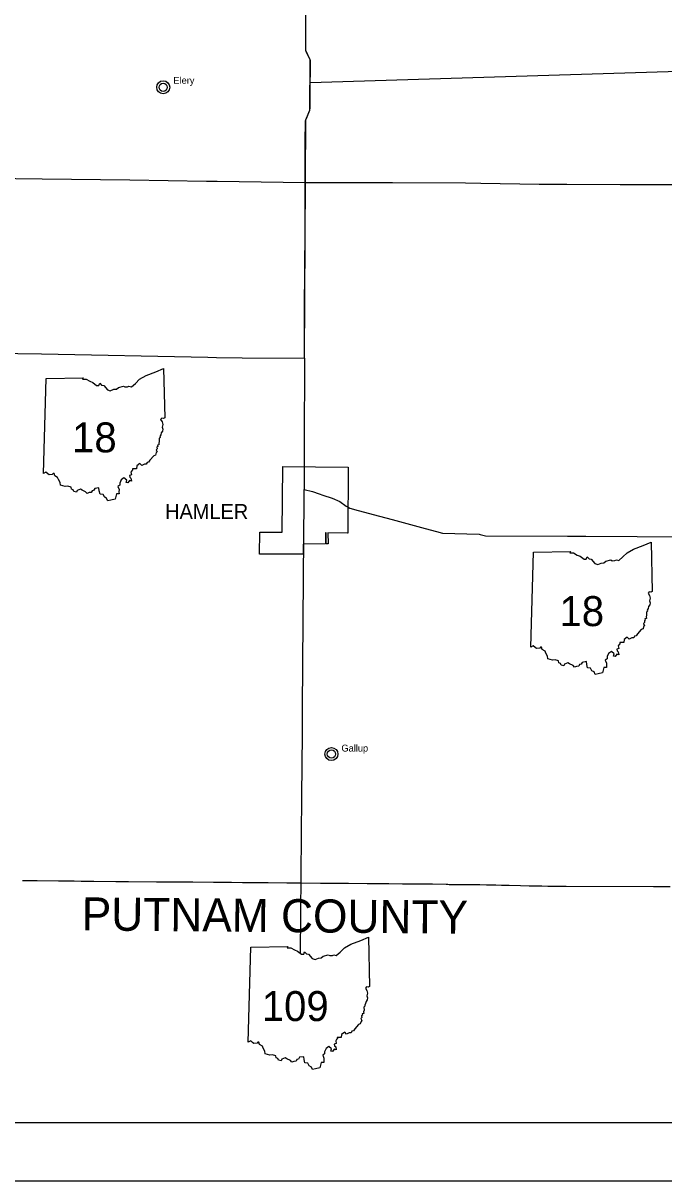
# Model space of a CAD drawing. Extents: x -62 to 810, y 0 to 440.
# Drawn here: x 310.9 to 421.2, y 0 to 199.3 of the extents above; entities that cross this region are included whole.
import ezdxf

# ---------------------------------------------------------------- set-up
doc = ezdxf.new("R2010")
doc.units = 0
for name, color, linetype in [('DV_X_Corp_Line', 7, 'Continuous'), ('GM_X_Adjacent_County_Text', 7, 'Continuous'), ('GM_X_Corporation_Text', 7, 'Continuous'), ('GM_X_County', 7, 'Continuous'), ('GM_X_State_Route', 7, 'Continuous'), ('PV_P_Text', 7, 'Continuous'), ('SH_Border', 7, 'Continuous'), ('SH_Cut_Line', 7, 'Continuous'), ('SH_Data', 7, 'Continuous'), ('SH_Text', 7, 'Continuous')]:
    doc.layers.add(name, color=color, linetype=linetype)

msp = doc.modelspace()

# ---------------------------------------------------------------- linework, layer by layer
at = {"layer": 'DV_X_Corp_Line'}
msp.add_lwpolyline([(351.66, 111.67), (355.46, 111.67), (355.59, 123), (366.85, 122.89), (366.8, 111.54), (366.73, 111.54), (363.35, 111.57), (363.38, 109.67), (363.07, 109.67), (363.07, 111.57), (362.92, 111.57), (362.92, 109.67), (359.12, 109.64), (359.09, 107.9), (355.36, 107.9), (351.6, 107.9)], close=True, dxfattribs=at)
for centre, radius in [((335, 188.28), 1.12), ((335, 188.28), 0.71), ((363.96, 73.49), 1.12), ((363.96, 73.49), 0.71)]:
    msp.add_circle(centre, radius, dxfattribs=at)
at = {"layer": 'GM_X_County'}
msp.add_lwpolyline([(310.77, 51.73), (313.34, 51.7), (317.01, 51.67), (319.67, 51.64), (320.86, 51.62), (323.04, 51.6), (326.88, 51.56), (329.03, 51.54), (333.87, 51.51), (334.27, 51.51), (337.68, 51.48), (340.12, 51.46), (343.65, 51.43), (346.75, 51.41), (348.67, 51.39), (350.87, 51.38), (353.07, 51.35), (356.3, 51.32), (358.75, 51.31), (358.78, 51.31), (362.05, 51.28), (363.97, 51.26), (366.23, 51.23), (366.9, 51.23), (370.08, 51.21), (373.83, 51.19), (376.16, 51.16), (381.35, 51.13), (383.69, 51.09), (383.93, 51.08), (384.01, 51.07), (384.23, 51.04), (384.37, 51.03), (388.07, 51.01), (388.79, 51), (388.87, 51), (389.28, 51.01), (389.49, 51.01), (390.64, 50.98), (392.27, 50.95), (393.21, 50.92), (393.91, 50.9), (394.57, 50.89), (396.49, 50.85), (397.99, 50.82), (399.11, 50.79), (400.14, 50.77), (401.22, 50.74), (402.67, 50.72), (403.42, 50.71), (404.09, 50.71), (404.33, 50.72), (419.38, 50.65), (419.65, 50.65), (420.14, 50.65), (422.24, 50.65)], dxfattribs=at)
at = {"layer": 'GM_X_State_Route'}
for points in [[(359.43, 171.91), (359.44, 180.11), (359.47, 181.2), (359.52, 182.5), (359.54, 182.65), (359.67, 182.93), (360.19, 184.2), (360.24, 184.32), (360.29, 184.75), (360.3, 187.08), (360.35, 192.84), (360.32, 193), (360.19, 193.26), (359.62, 194.44), (359.55, 194.64), (359.53, 195.17), (359.54, 202.27)], [(296.28, 172.8), (299.02, 172.75), (305.07, 172.65), (314.15, 172.51), (329.25, 172.33), (342.44, 172.14)], [(342.44, 172.14), (344.3, 172.11), (359.43, 171.91)], [(359.33, 144.8), (359.35, 150.27), (359.37, 156.78), (359.41, 163.71), (359.43, 169.07), (359.43, 171.91)], [(359.43, 171.91), (374.49, 171.9), (387.05, 171.82), (389.68, 171.77), (399.71, 171.62), (404.47, 171.59), (413.64, 171.54), (419.66, 171.53), (426.12, 171.52), (434.91, 171.57)], [(359.32, 141.66), (359.33, 144.8)], [(295.79, 142.57), (298.8, 142.55), (309.97, 142.42), (314.08, 142.4), (342.7, 141.81)], [(342.7, 141.81), (344.15, 141.77), (348.62, 141.7), (359.32, 141.66)], [(359.32, 141.66), (359.29, 126.7), (359.28, 122.43)], [(359.28, 122.43), (359.28, 122.15), (359.27, 119.01)], [(359.26, 117.79), (359.27, 117.98), (359.27, 119.01)], [(359.26, 116.99), (359.26, 117.79)], [(359.27, 119.01), (360.71, 118.66), (361.84, 118.29), (362.49, 118.08), (364.07, 117.56), (365.39, 116.98), (366.47, 116.16), (366.82, 115.97)], [(359.22, 111.6), (359.22, 111.6), (359.22, 112.56), (359.23, 113.43), (359.24, 114.37), (359.25, 115.41), (359.25, 116.04), (359.25, 116.22), (359.26, 116.77), (359.26, 116.99)], [(366.82, 115.97), (367.12, 115.81), (368.55, 115.42)], [(368.55, 115.42), (372.25, 114.43), (374.42, 113.84), (380.08, 112.32), (382.05, 111.78), (383.07, 111.51), (389.4, 111.32)], [(358.66, 39.16), (358.86, 66.24), (358.95, 76.89), (358.98, 81.38), (359.1, 96.45), (359.21, 110.82), (359.22, 111.6)], [(389.4, 111.32), (389.56, 111.31), (390.47, 111.04), (404.61, 111.01), (407.72, 110.99)], [(407.72, 110.99), (434.19, 110.83), (434.85, 110.83)]]:
    msp.add_lwpolyline(points, dxfattribs=at)
at = {"layer": 'PV_P_Text'}
for p, q in [((314.4, 121.77), (314.86, 138.14)), ((314.4, 121.77), (314.86, 138.14)), ((398.28, 91.86), (398.74, 108.24)), ((398.28, 91.86), (398.74, 108.24)), ((349.64, 23.86), (350.1, 40.23)), ((349.64, 23.86), (350.1, 40.23))]:
    msp.add_line(p, q, dxfattribs=at)
for points in [[(314.86, 138.14), (321.22, 138.25), (321.12, 138.05), (321.72, 138.01), (322.35, 137.66), (322.89, 137.44), (323.55, 136.92), (323.94, 136.92), (324.11, 137.35), (324.41, 137.02), (324.77, 136.96), (325.39, 136.18), (325.9, 136.01), (326.51, 136.28), (326.97, 136.32), (327.31, 136.59), (328.18, 136.81), (328.42, 136.68), (328.88, 136.7), (329.11, 136.8), (329.52, 136.71), (330.23, 137.31), (330.95, 138.01), (332.08, 138.67), (333.75, 139.3), (335.08, 139.86), (335.27, 131.37)], [(314.86, 138.14), (321.22, 138.25), (321.12, 138.05), (321.72, 138.01), (322.35, 137.66), (322.89, 137.44), (323.55, 136.92), (323.94, 136.92), (324.11, 137.35), (324.41, 137.02), (324.77, 136.96), (325.39, 136.18), (325.9, 136.01), (326.51, 136.28), (326.97, 136.32), (327.31, 136.59), (328.18, 136.81), (328.42, 136.68), (328.88, 136.7), (329.11, 136.8), (329.52, 136.71), (330.23, 137.31), (330.95, 138.01), (332.08, 138.67), (333.75, 139.3), (335.08, 139.86), (335.27, 131.37)], [(335.27, 131.37), (335.07, 131.25), (334.77, 131.3), (334.56, 131.06), (334.82, 130.67), (334.94, 130.25), (334.83, 129.78), (334.94, 129.4), (334.86, 129.08), (334.67, 128.76), (334.61, 128.46), (334.44, 128.14), (334.46, 127.96), (334.3, 127.82), (334.33, 127.29), (334.25, 126.99), (334.28, 126.74), (334.03, 126.67), (334.09, 126.46), (333.93, 126.3), (333.96, 126.02), (333.78, 125.85), (333.95, 125.49), (333.81, 125.38), (333.7, 124.94), (333.37, 124.85), (332.73, 124.06), (332.5, 123.76), (332.24, 123.69), (332.1, 123.38), (331.79, 123.38), (331.31, 123.16), (331, 123.53), (330.46, 123.09), (330.4, 122.58), (329.71, 122.6), (329.74, 122.34), (329.59, 122.26), (329.45, 122), (329.53, 121.54), (329.21, 121.43), (329.25, 121.16), (329.45, 121), (329.55, 120.49), (329.21, 120.59), (328.93, 120.16), (328.64, 120.26), (328.73, 120.63), (328.25, 121.06), (327.79, 120.71), (327.55, 120.15), (327.55, 119.78), (327.21, 119.55), (327.43, 119.02), (327.39, 118.65), (327.4, 118.3), (326.97, 118.31), (326.71, 117.37)], [(335.27, 131.37), (335.07, 131.25), (334.77, 131.3), (334.56, 131.06), (334.82, 130.67), (334.94, 130.25), (334.83, 129.78), (334.94, 129.4), (334.86, 129.08), (334.67, 128.76), (334.61, 128.46), (334.44, 128.14), (334.46, 127.96), (334.3, 127.82), (334.33, 127.29), (334.25, 126.99), (334.28, 126.74), (334.03, 126.67), (334.09, 126.46), (333.93, 126.3), (333.96, 126.02), (333.78, 125.85), (333.95, 125.49), (333.81, 125.38), (333.7, 124.94), (333.37, 124.85), (332.73, 124.06), (332.5, 123.76), (332.24, 123.69), (332.1, 123.38), (331.79, 123.38), (331.31, 123.16), (331, 123.53), (330.46, 123.09), (330.4, 122.58), (329.71, 122.6), (329.74, 122.34), (329.59, 122.26), (329.45, 122), (329.53, 121.54), (329.21, 121.43), (329.25, 121.16), (329.45, 121), (329.55, 120.49), (329.21, 120.59), (328.93, 120.16), (328.64, 120.26), (328.73, 120.63), (328.25, 121.06), (327.79, 120.71), (327.55, 120.15), (327.55, 119.78), (327.21, 119.55), (327.43, 119.02), (327.39, 118.65), (327.4, 118.3), (326.97, 118.31), (326.71, 117.37)], [(326.71, 117.37), (325.97, 117.19), (325.45, 117.09), (325.27, 117.51), (324.9, 117.74), (324.67, 118.17), (324.14, 118.23), (324.01, 118.82), (323.95, 119.3), (323.23, 119.18), (323.03, 118.88), (322.78, 118.81), (322.63, 118.51), (322.28, 118.49), (321.9, 118.35), (321.66, 118.64), (321.04, 118.93), (320.77, 119.08), (320.19, 118.84), (320.07, 118.57), (319.61, 118.69), (319.5, 119), (319.22, 119.09), (319.16, 119.42), (318.57, 119.59), (318.11, 119.52), (317.31, 119.78), (317.26, 120.21), (316.99, 120.73), (316.84, 121.1), (316.34, 121.37), (316.23, 121.81), (316.07, 121.79), (315.92, 121.62), (315.36, 121.54), (315.14, 121.71), (314.82, 122.02), (314.4, 121.77)], [(326.71, 117.37), (325.97, 117.19), (325.45, 117.09), (325.27, 117.51), (324.9, 117.74), (324.67, 118.17), (324.14, 118.23), (324.01, 118.82), (323.95, 119.3), (323.23, 119.18), (323.03, 118.88), (322.78, 118.81), (322.63, 118.51), (322.28, 118.49), (321.9, 118.35), (321.66, 118.64), (321.04, 118.93), (320.77, 119.08), (320.19, 118.84), (320.07, 118.57), (319.61, 118.69), (319.5, 119), (319.22, 119.09), (319.16, 119.42), (318.57, 119.59), (318.11, 119.52), (317.31, 119.78), (317.26, 120.21), (316.99, 120.73), (316.84, 121.1), (316.34, 121.37), (316.23, 121.81), (316.07, 121.79), (315.92, 121.62), (315.36, 121.54), (315.14, 121.71), (314.82, 122.02), (314.4, 121.77)], [(398.74, 108.24), (405.09, 108.34), (405, 108.14), (405.6, 108.1), (406.23, 107.75), (406.77, 107.53), (407.43, 107.01), (407.82, 107.02), (407.99, 107.44), (408.29, 107.12), (408.65, 107.06), (409.27, 106.27), (409.78, 106.1), (410.39, 106.37), (410.85, 106.42), (411.18, 106.68), (412.06, 106.91), (412.3, 106.77), (412.76, 106.8), (412.99, 106.9), (413.4, 106.81), (414.1, 107.41), (414.83, 108.11), (415.96, 108.77), (417.63, 109.4), (418.96, 109.96), (419.15, 101.46)], [(398.74, 108.24), (405.09, 108.34), (405, 108.14), (405.6, 108.1), (406.23, 107.75), (406.77, 107.53), (407.43, 107.01), (407.82, 107.02), (407.99, 107.44), (408.29, 107.12), (408.65, 107.06), (409.27, 106.27), (409.78, 106.1), (410.39, 106.37), (410.85, 106.42), (411.18, 106.68), (412.06, 106.91), (412.3, 106.77), (412.76, 106.8), (412.99, 106.9), (413.4, 106.81), (414.1, 107.41), (414.83, 108.11), (415.96, 108.77), (417.63, 109.4), (418.96, 109.96), (419.15, 101.46)], [(419.15, 101.46), (418.95, 101.34), (418.65, 101.4), (418.44, 101.16), (418.7, 100.76), (418.82, 100.34), (418.71, 99.88), (418.82, 99.5), (418.74, 99.18), (418.55, 98.86), (418.49, 98.56), (418.32, 98.24), (418.34, 98.06), (418.18, 97.92), (418.21, 97.39), (418.13, 97.09), (418.16, 96.84), (417.91, 96.77), (417.97, 96.56), (417.81, 96.4), (417.84, 96.12), (417.66, 95.94), (417.83, 95.58), (417.69, 95.47), (417.58, 95.04), (417.25, 94.95), (416.61, 94.16), (416.38, 93.86), (416.12, 93.78), (415.98, 93.47), (415.67, 93.47), (415.19, 93.26), (414.88, 93.63), (414.34, 93.19), (414.28, 92.68), (413.59, 92.69), (413.62, 92.43), (413.47, 92.36), (413.33, 92.1), (413.41, 91.64), (413.09, 91.52), (413.13, 91.26), (413.33, 91.09), (413.42, 90.58), (413.08, 90.69), (412.81, 90.26), (412.52, 90.36), (412.61, 90.72), (412.13, 91.16), (411.67, 90.81), (411.43, 90.25), (411.43, 89.87), (411.09, 89.64), (411.31, 89.11), (411.27, 88.74), (411.27, 88.4), (410.85, 88.41), (410.59, 87.47)], [(419.15, 101.46), (418.95, 101.34), (418.65, 101.4), (418.44, 101.16), (418.7, 100.76), (418.82, 100.34), (418.71, 99.88), (418.82, 99.5), (418.74, 99.18), (418.55, 98.86), (418.49, 98.56), (418.32, 98.24), (418.34, 98.06), (418.18, 97.92), (418.21, 97.39), (418.13, 97.09), (418.16, 96.84), (417.91, 96.77), (417.97, 96.56), (417.81, 96.4), (417.84, 96.12), (417.66, 95.94), (417.83, 95.58), (417.69, 95.47), (417.58, 95.04), (417.25, 94.95), (416.61, 94.16), (416.38, 93.86), (416.12, 93.78), (415.98, 93.47), (415.67, 93.47), (415.19, 93.26), (414.88, 93.63), (414.34, 93.19), (414.28, 92.68), (413.59, 92.69), (413.62, 92.43), (413.47, 92.36), (413.33, 92.1), (413.41, 91.64), (413.09, 91.52), (413.13, 91.26), (413.33, 91.09), (413.42, 90.58), (413.08, 90.69), (412.81, 90.26), (412.52, 90.36), (412.61, 90.72), (412.13, 91.16), (411.67, 90.81), (411.43, 90.25), (411.43, 89.87), (411.09, 89.64), (411.31, 89.11), (411.27, 88.74), (411.27, 88.4), (410.85, 88.41), (410.59, 87.47)], [(410.59, 87.47), (409.85, 87.29), (409.33, 87.18), (409.15, 87.61), (408.78, 87.83), (408.54, 88.26), (408.02, 88.32), (407.89, 88.91), (407.83, 89.39), (407.11, 89.27), (406.91, 88.98), (406.66, 88.9), (406.51, 88.61), (406.16, 88.58), (405.78, 88.44), (405.54, 88.73), (404.92, 89.02), (404.65, 89.17), (404.07, 88.94), (403.95, 88.66), (403.49, 88.79), (403.38, 89.09), (403.1, 89.19), (403.04, 89.51), (402.44, 89.68), (401.99, 89.62), (401.19, 89.88), (401.14, 90.31), (400.87, 90.83), (400.72, 91.19), (400.22, 91.47), (400.11, 91.9), (399.95, 91.89), (399.8, 91.71), (399.24, 91.63), (399.02, 91.81), (398.7, 92.11), (398.28, 91.86)], [(410.59, 87.47), (409.85, 87.29), (409.33, 87.18), (409.15, 87.61), (408.78, 87.83), (408.54, 88.26), (408.02, 88.32), (407.89, 88.91), (407.83, 89.39), (407.11, 89.27), (406.91, 88.98), (406.66, 88.9), (406.51, 88.61), (406.16, 88.58), (405.78, 88.44), (405.54, 88.73), (404.92, 89.02), (404.65, 89.17), (404.07, 88.94), (403.95, 88.66), (403.49, 88.79), (403.38, 89.09), (403.1, 89.19), (403.04, 89.51), (402.44, 89.68), (401.99, 89.62), (401.19, 89.88), (401.14, 90.31), (400.87, 90.83), (400.72, 91.19), (400.22, 91.47), (400.11, 91.9), (399.95, 91.89), (399.8, 91.71), (399.24, 91.63), (399.02, 91.81), (398.7, 92.11), (398.28, 91.86)], [(350.1, 40.23), (356.45, 40.34), (356.35, 40.14), (356.95, 40.1), (357.59, 39.75), (358.13, 39.53), (358.79, 39.01), (359.18, 39.01), (359.35, 39.44), (359.65, 39.11), (360.01, 39.05), (360.63, 38.27), (361.14, 38.1), (361.75, 38.36), (362.21, 38.41), (362.54, 38.67), (363.41, 38.9), (363.66, 38.77), (364.12, 38.79), (364.35, 38.89), (364.75, 38.8), (365.46, 39.4), (366.19, 40.1), (367.31, 40.76), (368.99, 41.39), (370.32, 41.95), (370.51, 33.45)], [(350.1, 40.23), (356.45, 40.34), (356.35, 40.14), (356.95, 40.1), (357.59, 39.75), (358.13, 39.53), (358.79, 39.01), (359.18, 39.01), (359.35, 39.44), (359.65, 39.11), (360.01, 39.05), (360.63, 38.27), (361.14, 38.1), (361.75, 38.36), (362.21, 38.41), (362.54, 38.67), (363.41, 38.9), (363.66, 38.77), (364.12, 38.79), (364.35, 38.89), (364.75, 38.8), (365.46, 39.4), (366.19, 40.1), (367.31, 40.76), (368.99, 41.39), (370.32, 41.95), (370.51, 33.45)], [(370.51, 33.45), (370.31, 33.34), (370.01, 33.39), (369.8, 33.15), (370.06, 32.76), (370.18, 32.34), (370.07, 31.87), (370.17, 31.49), (370.1, 31.17), (369.91, 30.85), (369.84, 30.55), (369.68, 30.23), (369.7, 30.05), (369.54, 29.91), (369.57, 29.38), (369.49, 29.08), (369.52, 28.83), (369.27, 28.76), (369.32, 28.55), (369.16, 28.39), (369.2, 28.11), (369.02, 27.93), (369.19, 27.58), (369.05, 27.46), (368.93, 27.03), (368.61, 26.94), (367.96, 26.15), (367.74, 25.85), (367.48, 25.78), (367.34, 25.47), (367.02, 25.47), (366.55, 25.25), (366.24, 25.62), (365.7, 25.18), (365.64, 24.67), (364.95, 24.68), (364.98, 24.43), (364.83, 24.35), (364.69, 24.09), (364.77, 23.63), (364.45, 23.52), (364.49, 23.25), (364.69, 23.09), (364.78, 22.58), (364.44, 22.68), (364.16, 22.25), (363.88, 22.35), (363.97, 22.71), (363.49, 23.15), (363.03, 22.8), (362.79, 22.24), (362.79, 21.86), (362.45, 21.64), (362.67, 21.1), (362.63, 20.74), (362.63, 20.39), (362.21, 20.4), (361.95, 19.46)], [(370.51, 33.45), (370.31, 33.34), (370.01, 33.39), (369.8, 33.15), (370.06, 32.76), (370.18, 32.34), (370.07, 31.87), (370.17, 31.49), (370.1, 31.17), (369.91, 30.85), (369.84, 30.55), (369.68, 30.23), (369.7, 30.05), (369.54, 29.91), (369.57, 29.38), (369.49, 29.08), (369.52, 28.83), (369.27, 28.76), (369.32, 28.55), (369.16, 28.39), (369.2, 28.11), (369.02, 27.93), (369.19, 27.58), (369.05, 27.46), (368.93, 27.03), (368.61, 26.94), (367.96, 26.15), (367.74, 25.85), (367.48, 25.78), (367.34, 25.47), (367.02, 25.47), (366.55, 25.25), (366.24, 25.62), (365.7, 25.18), (365.64, 24.67), (364.95, 24.68), (364.98, 24.43), (364.83, 24.35), (364.69, 24.09), (364.77, 23.63), (364.45, 23.52), (364.49, 23.25), (364.69, 23.09), (364.78, 22.58), (364.44, 22.68), (364.16, 22.25), (363.88, 22.35), (363.97, 22.71), (363.49, 23.15), (363.03, 22.8), (362.79, 22.24), (362.79, 21.86), (362.45, 21.64), (362.67, 21.1), (362.63, 20.74), (362.63, 20.39), (362.21, 20.4), (361.95, 19.46)], [(361.95, 19.46), (361.21, 19.28), (360.69, 19.17), (360.51, 19.6), (360.14, 19.83), (359.9, 20.26), (359.37, 20.32), (359.25, 20.91), (359.19, 21.38), (358.47, 21.27), (358.27, 20.97), (358.01, 20.89), (357.86, 20.6), (357.51, 20.57), (357.14, 20.44), (356.9, 20.72), (356.28, 21.02), (356, 21.17), (355.43, 20.93), (355.3, 20.66), (354.84, 20.78), (354.74, 21.09), (354.46, 21.18), (354.4, 21.5), (353.8, 21.68), (353.35, 21.61), (352.55, 21.87), (352.5, 22.3), (352.22, 22.82), (352.08, 23.19), (351.57, 23.46), (351.47, 23.9), (351.31, 23.88), (351.16, 23.71), (350.6, 23.63), (350.37, 23.8), (350.06, 24.1), (349.64, 23.86)], [(361.95, 19.46), (361.21, 19.28), (360.69, 19.17), (360.51, 19.6), (360.14, 19.83), (359.9, 20.26), (359.37, 20.32), (359.25, 20.91), (359.19, 21.38), (358.47, 21.27), (358.27, 20.97), (358.01, 20.89), (357.86, 20.6), (357.51, 20.57), (357.14, 20.44), (356.9, 20.72), (356.28, 21.02), (356, 21.17), (355.43, 20.93), (355.3, 20.66), (354.84, 20.78), (354.74, 21.09), (354.46, 21.18), (354.4, 21.5), (353.8, 21.68), (353.35, 21.61), (352.55, 21.87), (352.5, 22.3), (352.22, 22.82), (352.08, 23.19), (351.57, 23.46), (351.47, 23.9), (351.31, 23.88), (351.16, 23.71), (350.6, 23.63), (350.37, 23.8), (350.06, 24.1), (349.64, 23.86)]]:
    msp.add_lwpolyline(points, dxfattribs=at)
at = {"layer": 'SH_Border'}
msp.add_lwpolyline([(30, 430), (670, 430), (670, 10), (30, 10)], close=True, dxfattribs=at)
at = {"layer": 'SH_Cut_Line'}
msp.add_lwpolyline([(0, 0), (680, 0), (680, 440), (0, 440)], close=True, dxfattribs=at)
at = {"layer": 'SH_Data'}
msp.add_line((487.96, 193), (360.28, 189.02), dxfattribs=at)
at = {"layer": 'SH_Text'}
for p, q in [((359.55, 194.64), (359.54, 202.27)), ((360.32, 193), (359.55, 194.64)), ((360.24, 184.32), (360.32, 193)), ((359.54, 182.65), (360.24, 184.32)), ((359.32, 141.66), (359.54, 182.65))]:
    msp.add_line(p, q, dxfattribs=at)

# ---------------------------------------------------------------- texts
at = {"layer": 'GM_X_Adjacent_County_Text'}
msp.add_text('PUTNAM COUNTY', height=5.7, rotation=359.4991, dxfattribs=at).set_placement((320.96, 43.12))
at = {"layer": 'GM_X_Corporation_Text'}
for s, height, p in [('Elery', 1.188, (336.76, 188.88)), ('HAMLER', 2.565, (335.34, 113.97)), ('Gallup', 1.188, (365.68, 73.91))]:
    msp.add_text(s, height=height, rotation=0, dxfattribs=at).set_placement(p)
at = {"layer": 'PV_P_Text'}
for s, p in [('18', (319.32, 125.42)), ('18', (403.2, 95.51)), ('109', (351.97, 27.51))]:
    msp.add_text(s, height=5.162, dxfattribs=at).set_placement(p)

doc.saveas('drawing.dxf')
